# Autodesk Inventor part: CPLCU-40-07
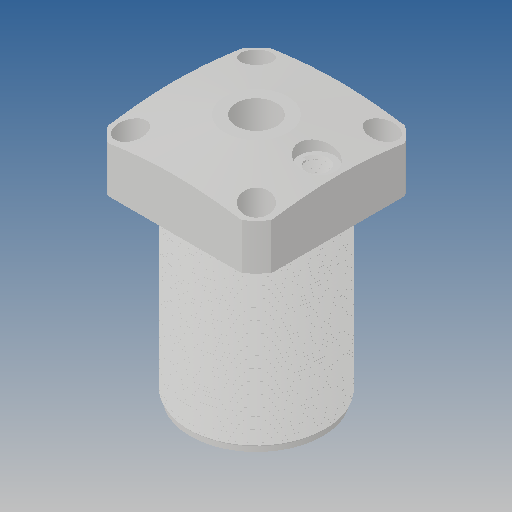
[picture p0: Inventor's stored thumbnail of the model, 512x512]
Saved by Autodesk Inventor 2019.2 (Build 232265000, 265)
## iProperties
Created: 2010-03
Part Number: CPLCU-40-07
Material: Ogólny
Document SubType Name: Modeling
Designer: CADENGINEERING4
Density: 1 g/cm^3
Appearance: Domyślna
Author: CADENGINEERING4
Revision Number: 5LAST_VERSION
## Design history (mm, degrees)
feature "Baza1"
node "Bryła1"
